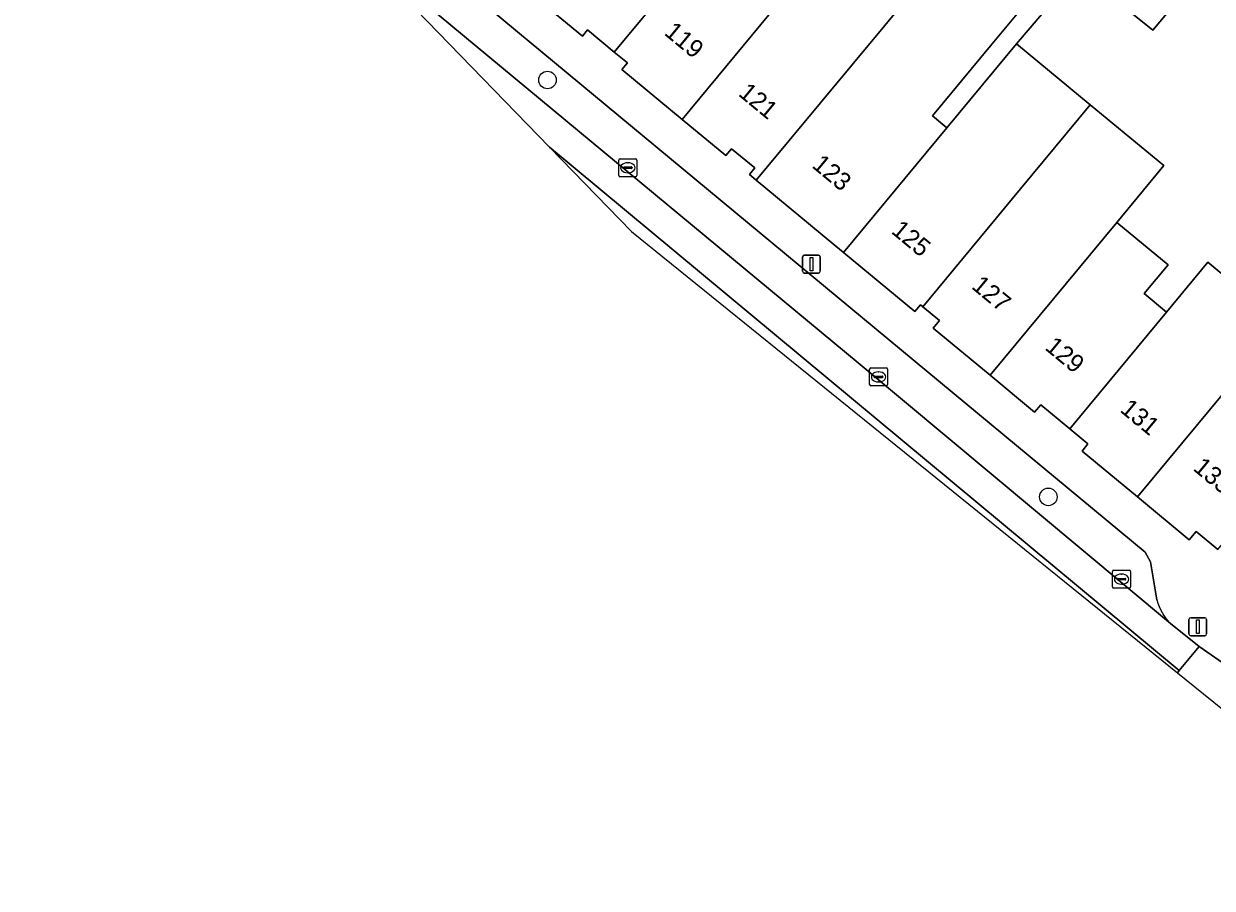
# Model space of a CAD drawing. Extents: x 162073 to 163043, y 381818 to 382561.
# Drawn here: x 162313.8 to 162380.1, y 381927.9 to 381976.1 of the extents above; entities that cross this region are included whole.
import ezdxf

# ---------------------------------------------------------------- set-up
doc = ezdxf.new("R2010")
doc.units = 0
for name, color, linetype in [('IMGEO_Boom', 7, 'Continuous'), ('IMGEO_Erf', 7, 'Continuous'), ('IMGEO_Kolk', 7, 'Continuous'), ('IMGEO_Lichtmast', 7, 'Continuous'), ('IMGEO_Pand', 7, 'Continuous'), ('IMGEO_Pand_nummerreeks', 7, 'Continuous'), ('IMGEO_Parkeervlak_open', 7, 'Continuous'), ('IMGEO_Rijbaan_lokaal_gesloten', 7, 'Continuous'), ('IMGEO_Rijbaan_lokaal_open', 7, 'Continuous'), ('IMGEO_Voetpad_open', 7, 'Continuous')]:
    doc.layers.add(name, color=color, linetype=linetype)

msp = doc.modelspace()

# ---------------------------------------------------------------- linework, layer by layer
at = {"layer": 'IMGEO_Boom'}
for centre in [(162342.989, 381972.955), (162370.946, 381949.697)]:
    msp.add_circle(centre, 0.489, dxfattribs=at)
at = {"layer": 'IMGEO_Erf'}
msp.add_lwpolyline([(162378.731, 381978.074), (162376.782, 381975.739), (162372.639, 381979.056), (162369.166, 381974.973), (162373.282, 381971.567), (162377.383, 381968.174), (162374.762, 381965.007), (162377.625, 381962.637), (162376.299, 381961.035), (162377.54, 381960.007), (162379.844, 381962.782), (162383.946, 381959.377)], dxfattribs=at)
at = {"layer": 'IMGEO_Kolk'}
for p, q in [((162346.975, 381967.632), (162346.975, 381968.484)), ((162347.05, 381968.558), (162347.902, 381968.558)), ((162347.976, 381968.484), (162347.976, 381967.632)), ((162347.234, 381968.052), (162347.234, 381968.064)), ((162347.672, 381968.015), (162347.274, 381968.015)), ((162347.277, 381968.101), (162347.675, 381968.101)), ((162347.463, 381968.338), (162347.488, 381968.338)), ((162347.718, 381968.064), (162347.718, 381968.052)), ((162347.902, 381967.558), (162347.05, 381967.558)), ((162347.486, 381967.778), (162347.461, 381967.778)), ((162360.967, 381955.965), (162360.967, 381956.817)), ((162361.042, 381956.891), (162361.894, 381956.891)), ((162361.455, 381956.671), (162361.48, 381956.671)), ((162361.968, 381956.817), (162361.968, 381955.965)), ((162361.894, 381955.891), (162361.042, 381955.891)), ((162361.226, 381956.385), (162361.226, 381956.397)), ((162361.664, 381956.348), (162361.266, 381956.348)), ((162361.269, 381956.434), (162361.667, 381956.434)), ((162361.478, 381956.111), (162361.453, 381956.111)), ((162361.71, 381956.397), (162361.71, 381956.385)), ((162374.527, 381944.683), (162374.527, 381945.535)), ((162374.602, 381945.609), (162375.454, 381945.609)), ((162375.015, 381945.389), (162375.04, 381945.389)), ((162375.528, 381945.535), (162375.528, 381944.683)), ((162375.454, 381944.609), (162374.602, 381944.609)), ((162374.786, 381945.103), (162374.786, 381945.115)), ((162375.224, 381945.066), (162374.826, 381945.066)), ((162374.829, 381945.152), (162375.227, 381945.152)), ((162375.038, 381944.829), (162375.013, 381944.829)), ((162375.27, 381945.115), (162375.27, 381945.103))]:
    msp.add_line(p, q, dxfattribs=at)
for points in [[(162346.975, 381967.632), (162346.975, 381968.484)], [(162347.05, 381968.558), (162347.902, 381968.558)], [(162347.976, 381968.484), (162347.976, 381967.632)], [(162347.902, 381967.558), (162347.05, 381967.558)], [(162360.967, 381955.965), (162360.967, 381956.817)], [(162361.042, 381956.891), (162361.894, 381956.891)], [(162361.968, 381956.817), (162361.968, 381955.965)], [(162361.894, 381955.891), (162361.042, 381955.891)], [(162374.527, 381944.683), (162374.527, 381945.535)], [(162374.602, 381945.609), (162375.454, 381945.609)], [(162375.528, 381945.535), (162375.528, 381944.683)], [(162375.454, 381944.609), (162374.602, 381944.609)]]:
    msp.add_lwpolyline(points, dxfattribs=at)
for centre, radius, start, end in [((162347.052, 381968.482), 0.0765, 91.55205, 178.44795), ((162347.052, 381968.482), 0.0765, 91.55205, 178.44795), ((162347.9, 381968.482), 0.0765, 1.55205, 88.44795), ((162347.9, 381968.482), 0.0765, 1.55205, 88.44795), ((162347.274, 381968.061), 0.0403, 85.87752, 175.75265), ((162347.271, 381968.051), 0.0366, 178.93798, 274.71019), ((162347.675, 381968.058), 0.043, 264.86636, 352.45326), ((162347.679, 381968.063), 0.0386, 1.73085, 96.63898), ((162347.052, 381967.634), 0.0765, 181.55205, 268.44795), ((162347.052, 381967.634), 0.0765, 181.55205, 268.44795), ((162347.9, 381967.634), 0.0765, 271.55205, 358.44795), ((162347.9, 381967.634), 0.0765, 271.55205, 358.44795), ((162361.044, 381956.815), 0.0765, 91.55205, 178.44795), ((162361.044, 381956.815), 0.0765, 91.55205, 178.44795), ((162361.892, 381956.815), 0.0765, 1.55205, 88.44795), ((162361.892, 381956.815), 0.0765, 1.55205, 88.44795), ((162361.044, 381955.967), 0.0765, 181.55205, 268.44795), ((162361.044, 381955.967), 0.0765, 181.55205, 268.44795), ((162361.266, 381956.394), 0.0403, 85.87752, 175.75265), ((162361.263, 381956.384), 0.0366, 178.93798, 274.71019), ((162361.667, 381956.391), 0.043, 264.86636, 352.45326), ((162361.671, 381956.396), 0.0386, 1.73085, 96.63898), ((162361.892, 381955.967), 0.0765, 271.55205, 358.44795), ((162361.892, 381955.967), 0.0765, 271.55205, 358.44795), ((162374.604, 381945.533), 0.0765, 91.55205, 178.44795), ((162374.604, 381945.533), 0.0765, 91.55205, 178.44795), ((162375.452, 381945.533), 0.0765, 1.55205, 88.44795), ((162375.452, 381945.533), 0.0765, 1.55205, 88.44795), ((162374.604, 381944.685), 0.0765, 181.55205, 268.44795), ((162374.604, 381944.685), 0.0765, 181.55205, 268.44795), ((162374.826, 381945.112), 0.0403, 85.87752, 175.75265), ((162374.823, 381945.102), 0.0366, 178.93798, 274.71019), ((162375.227, 381945.109), 0.043, 264.86636, 352.45326), ((162375.231, 381945.114), 0.0386, 1.73085, 96.63898), ((162375.452, 381944.685), 0.0765, 271.55205, 358.44795), ((162375.452, 381944.685), 0.0765, 271.55205, 358.44795)]:
    msp.add_arc(centre, radius, start, end, dxfattribs=at)
for centre, major_axis, ratio, start_param, end_param in [((162347.462, 381968.058), (-0.387, 0.002), 0.722429, 4.712389, 7.853982), ((162347.487, 381968.058), (-0.39, 0.002), 0.717154, 1.570796, 4.712389), ((162361.454, 381956.391), (-0.387, 0.002), 0.722429, 4.712389, 7.853982), ((162361.479, 381956.391), (-0.39, 0.002), 0.717154, 1.570796, 4.712389), ((162375.014, 381945.109), (-0.387, 0.002), 0.722429, 4.712389, 7.853982), ((162375.039, 381945.109), (-0.39, 0.002), 0.717154, 1.570796, 4.712389)]:
    msp.add_ellipse(centre, major_axis=major_axis, ratio=ratio, start_param=start_param, end_param=end_param, dxfattribs=at)
at = {"layer": 'IMGEO_Lichtmast'}
for p, q in [((162357.322, 381963.182), (162358.112, 381963.182)), ((162358.112, 381963.182), (162357.322, 381963.182)), ((162357.222, 381962.282), (162357.222, 381963.082)), ((162357.222, 381963.082), (162357.222, 381962.282)), ((162358.212, 381963.082), (162358.212, 381962.282)), ((162358.212, 381962.282), (162358.212, 381963.082)), ((162358.112, 381962.182), (162357.322, 381962.182)), ((162357.322, 381962.182), (162358.112, 381962.182)), ((162378.786, 381942.056), (162378.786, 381942.856)), ((162378.786, 381942.856), (162378.786, 381942.056)), ((162378.886, 381942.956), (162379.676, 381942.956)), ((162379.676, 381942.956), (162378.886, 381942.956)), ((162379.776, 381942.856), (162379.776, 381942.056)), ((162379.776, 381942.056), (162379.776, 381942.856)), ((162379.676, 381941.956), (162378.886, 381941.956)), ((162378.886, 381941.956), (162379.676, 381941.956))]:
    msp.add_line(p, q, dxfattribs=at)
for points in [[(162357.642, 381963.057), (162357.792, 381963.057), (162357.792, 381962.307), (162357.642, 381962.307), (162357.642, 381963.057)], [(162379.206, 381942.831), (162379.356, 381942.831), (162379.356, 381942.081), (162379.206, 381942.081), (162379.206, 381942.831)]]:
    msp.add_lwpolyline(points, dxfattribs=at)
for centre, start, end in [((162357.322, 381963.082), 90, 180), ((162357.322, 381963.082), 90, 180), ((162358.112, 381963.082), 0, 90), ((162358.112, 381963.082), 360, 90), ((162357.322, 381962.282), 180, 270), ((162357.322, 381962.282), 180, 270), ((162358.112, 381962.282), 270, 0), ((162358.112, 381962.282), 270, 0), ((162378.886, 381942.856), 90, 180), ((162378.886, 381942.856), 90, 180), ((162379.676, 381942.856), 0, 90), ((162379.676, 381942.856), 360, 90), ((162378.886, 381942.056), 180, 270), ((162378.886, 381942.056), 180, 270), ((162379.676, 381942.056), 270, 0), ((162379.676, 381942.056), 270, 0)]:
    msp.add_arc(centre, 0.1, start, end, dxfattribs=at)
at = {"layer": 'IMGEO_Pand'}
for points in [[(162351.093, 381984.956), (162349.531, 381986.253), (162348.116, 381984.548), (162342.323, 381977.568), (162344.938, 381975.403), (162345.224, 381975.748), (162346.715, 381974.514), (162352.251, 381981.184), (162354.115, 381983.43), (162358.982, 381989.294), (162356.443, 381991.401)], [(162363.656, 381978.23), (162363.42, 381978.425), (162364.77, 381980.055), (162363.031, 381981.494), (162365.726, 381984.749), (162367.712, 381983.105), (162367.859, 381983.282), (162369.884, 381985.729), (162367.898, 381987.373), (162365.776, 381989.13), (162358.526, 381980.451), (162356.335, 381977.804), (162350.514, 381970.745), (162352.944, 381968.733), (162353.264, 381969.12), (162354.562, 381968.046), (162354.264, 381967.685), (162354.643, 381967.372)], [(162356.335, 381977.804), (162354.21, 381979.563), (162352.251, 381981.184), (162346.715, 381974.514), (162347.448, 381973.907), (162347.142, 381973.537), (162350.514, 381970.745)], [(162374.54, 381981.43), (162372.639, 381979.056), (162376.782, 381975.739), (162378.731, 381978.074)], [(162364.475, 381970.946), (162367.72, 381974.865), (162370.033, 381977.658), (162367.491, 381979.763), (162365.179, 381976.969), (162363.656, 381978.23), (162354.643, 381967.372), (162359.517, 381963.336), (162365.281, 381970.278)], [(162373.282, 381971.567), (162369.166, 381974.973), (162365.281, 381970.278), (162359.517, 381963.336), (162363.494, 381960.043), (162363.801, 381960.414), (162363.931, 381960.306), (162369.388, 381966.878)], [(162367.692, 381956.491), (162374.762, 381965.007), (162377.383, 381968.174), (162373.282, 381971.567), (162369.388, 381966.878), (162363.931, 381960.306), (162364.865, 381959.533), (162364.52, 381959.117)], [(162367.692, 381956.491), (162370.179, 381954.431), (162370.516, 381954.837), (162372.135, 381953.497), (162377.54, 381960.007), (162376.299, 381961.035), (162377.625, 381962.637), (162374.762, 381965.007)], [(162381.646, 381956.606), (162383.946, 381959.377), (162379.844, 381962.782), (162377.54, 381960.007), (162372.135, 381953.497), (162373.154, 381952.653), (162372.824, 381952.254), (162375.911, 381949.698)], [(162381.646, 381956.606), (162375.911, 381949.698), (162378.804, 381947.303), (162379.189, 381947.768), (162380.402, 381946.763), (162385.751, 381953.206)]]:
    msp.add_lwpolyline(points, close=True, dxfattribs=at)
at = {"layer": 'IMGEO_Parkeervlak_open'}
for points in [[(162377.001, 381943.955), (162376.642, 381946.078), (162376.347, 381946.606), (162338.377, 381978.091)], [(162336.192, 381977.174), (162360.336, 381957.182), (162377.76, 381942.629)]]:
    msp.add_lwpolyline(points, dxfattribs=at)
msp.add_arc((162379.794, 381944.674), 2.884, 194.4275, 225.14599, dxfattribs=at)
at = {"layer": 'IMGEO_Rijbaan_lokaal_gesloten'}
msp.add_lwpolyline([(162320.032, 381992.987), (162336.285, 381976.241), (162343.107, 381969.212), (162378.252, 381940.019), (162379.368, 381941.362), (162377.76, 381942.629), (162360.336, 381957.182), (162336.192, 381977.174), (162335.406, 381977.868), (162330.031, 381984.072), (162321.544, 381993.865), (162321.47, 381993.951), (162318.3, 381997.607), (162314.924, 382001.511), (162278.959, 382042.995), (162278.707, 382042.779), (162277.631, 382041.861), (162320.032, 381992.987)], dxfattribs=at)
at = {"layer": 'IMGEO_Rijbaan_lokaal_open'}
for points in [[(162343.107, 381969.212), (162347.686, 381964.494), (162378.151, 381939.893), (162378.252, 381940.019), (162343.107, 381969.212)], [(162380.891, 381940.302), (162379.368, 381941.362), (162378.252, 381940.019), (162378.151, 381939.893), (162393.04, 381927.87)]]:
    msp.add_lwpolyline(points, dxfattribs=at)
at = {"layer": 'IMGEO_Voetpad_open'}
for points in [[(162353.264, 381969.12), (162352.944, 381968.733), (162350.514, 381970.745), (162347.142, 381973.537), (162347.448, 381973.907), (162346.715, 381974.514), (162345.224, 381975.748), (162344.938, 381975.403), (162342.323, 381977.568), (162338.731, 381980.542), (162339.136, 381981.03), (162338.614, 381981.6), (162337.232, 381983.109), (162336.754, 381982.694), (162334.093, 381985.758), (162330.964, 381989.359), (162327.47, 381993.382), (162323.824, 381997.579), (162322.239, 381999.395), (162321.711, 382000), (162317.658, 382004.641), (162314.351, 382008.426), (162309.002, 382014.551)], [(162338.377, 381978.091), (162376.347, 381946.606), (162376.642, 381946.078), (162377.001, 381943.955)], [(162380.402, 381946.763), (162379.189, 381947.768), (162378.804, 381947.303), (162375.911, 381949.698), (162372.824, 381952.254), (162373.154, 381952.653), (162372.135, 381953.497), (162370.516, 381954.837), (162370.179, 381954.431), (162367.692, 381956.491), (162364.52, 381959.117), (162364.865, 381959.533), (162363.931, 381960.306), (162363.801, 381960.414), (162363.494, 381960.043), (162359.517, 381963.336), (162354.643, 381967.372), (162354.264, 381967.685), (162354.562, 381968.046), (162353.264, 381969.12)], [(162377.76, 381942.629), (162379.368, 381941.362), (162380.891, 381940.302)]]:
    msp.add_lwpolyline(points, dxfattribs=at)
msp.add_lwpolyline([(162359.639, 381995.79), (162355.439, 381999.143), (162354.7, 381998.299), (162364.311, 381990.342), (162365.776, 381989.13), (162367.898, 381987.373), (162369.884, 381985.729), (162371.722, 381984.208), (162373.067, 381983.093), (162373.067, 381981.323), (162372.453, 381980.581), (162370.033, 381977.658), (162367.72, 381974.865), (162364.475, 381970.946), (162365.281, 381970.278), (162369.166, 381974.973), (162372.639, 381979.056), (162374.54, 381981.43), (162375.442, 381982.522), (162374.962, 381982.918), (162373.791, 381983.885), (162373.714, 381983.795), (162367.823, 381988.815), (162365.411, 381990.87)], close=True, dxfattribs=at)
msp.add_arc((162379.794, 381944.674), 2.884, 194.4275, 225.14599, dxfattribs=at)

# ---------------------------------------------------------------- texts
at = {"layer": 'IMGEO_Pand_nummerreeks'}
for s, rotation, p in [('119', 320.37997, (162349.453, 381975.517)), ('121', 320.39716, (162353.59, 381972.121)), ('123', 320.3857, (162357.696, 381968.117)), ('125', 320.35924, (162362.123, 381964.451)), ('127', 320.37499, (162366.601, 381961.368)), ('129', 320.37864, (162370.698, 381957.958)), ('131', 320.37864, (162374.891, 381954.486)), ('133', 320.37933, (162378.966, 381951.225))]:
    msp.add_text(s, height=1, rotation=rotation, dxfattribs=at).set_placement(p)

doc.saveas('drawing.dxf')
